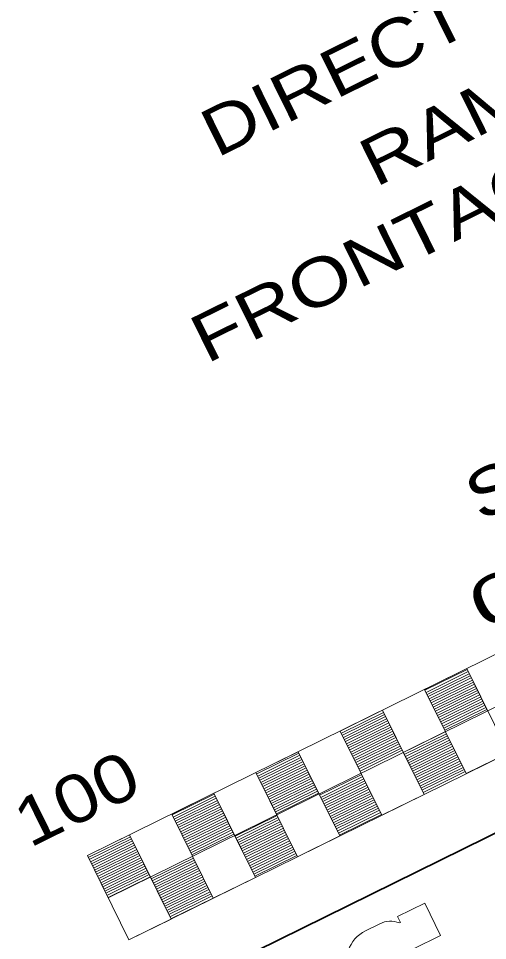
# Model space of a CAD drawing. Extents: x 2356606 to 2371222, y 6973096 to 6982644.
# Drawn here: x 2358140.4 to 2358240.2, y 6973453.7 to 6973650.2 of the extents above; entities that cross this region are included whole.
import ezdxf
from ezdxf.enums import TextEntityAlignment as Align

# ---------------------------------------------------------------- set-up
doc = ezdxf.new("R2010")
doc.units = 0
doc.header["$LTSCALE"] = 2
doc.layers.add('62', color=7, linetype='Continuous', lineweight=13)
doc.layers.add('63', color=7, linetype='Continuous', lineweight=13)

msp = doc.modelspace()

# ---------------------------------------------------------------- linework, layer by layer
at = {"layer": '62', "lineweight": 35}
msp.add_line((2358728.863, 6973716.998), (2358145.069, 6973428.875), dxfattribs=at)
at = {"layer": '62'}
for p, q in [((2358155.076, 6973471.825), (2358513.803, 6973648.869)), ((2358159.503, 6973462.857), (2358518.229, 6973639.901)), ((2358226.91, 6973507.057), (2358235.878, 6973511.484)), ((2358227.13, 6973506.608), (2358236.098, 6973511.034)), ((2358227.352, 6973506.158), (2358236.321, 6973510.585)), ((2358227.573, 6973505.71), (2358236.541, 6973510.137)), ((2358235.79, 6973511.66), (2358240.215, 6973502.692)), ((2358227.795, 6973505.262), (2358236.764, 6973509.688)), ((2358228.017, 6973504.813), (2358236.985, 6973509.24)), ((2358228.237, 6973504.365), (2358237.205, 6973508.791)), ((2358228.458, 6973503.917), (2358237.427, 6973508.343)), ((2358228.679, 6973503.469), (2358237.647, 6973507.895)), ((2358226.822, 6973507.233), (2358231.247, 6973498.265)), ((2358228.901, 6973503.021), (2358237.869, 6973507.446)), ((2358229.123, 6973502.572), (2358238.09, 6973506.998)), ((2358229.343, 6973502.124), (2358238.313, 6973506.549)), ((2358229.566, 6973501.675), (2358238.534, 6973506.101)), ((2358229.787, 6973501.227), (2358238.755, 6973505.652)), ((2358230.008, 6973500.779), (2358238.976, 6973505.204)), ((2358230.229, 6973500.33), (2358239.197, 6973504.756)), ((2358230.449, 6973499.882), (2358239.419, 6973504.307)), ((2358208.89, 6973498.371), (2358217.859, 6973502.798)), ((2358209.111, 6973497.922), (2358218.08, 6973502.349)), ((2358217.854, 6973502.808), (2358222.28, 6973493.84)), ((2358230.671, 6973499.433), (2358239.639, 6973503.859)), ((2358230.892, 6973498.985), (2358239.862, 6973503.411)), ((2358231.115, 6973498.537), (2358240.082, 6973502.962)), ((2358209.334, 6973497.472), (2358218.301, 6973501.899)), ((2358209.556, 6973497.024), (2358218.522, 6973501.452)), ((2358209.776, 6973496.576), (2358218.744, 6973501.002)), ((2358209.997, 6973496.128), (2358218.966, 6973500.554)), ((2358210.219, 6973495.681), (2358219.186, 6973500.106)), ((2358208.885, 6973498.381), (2358213.31, 6973489.414)), ((2358210.439, 6973495.231), (2358219.408, 6973499.657)), ((2358210.662, 6973494.783), (2358219.63, 6973499.209)), ((2358210.883, 6973494.335), (2358219.85, 6973498.761)), ((2358211.103, 6973493.886), (2358220.072, 6973498.313)), ((2358222.284, 6973493.829), (2358231.253, 6973498.256)), ((2358211.324, 6973493.439), (2358220.294, 6973497.863)), ((2358211.546, 6973492.989), (2358220.514, 6973497.415)), ((2358211.768, 6973492.541), (2358220.735, 6973496.967)), ((2358211.988, 6973492.093), (2358220.957, 6973496.519)), ((2358212.21, 6973491.644), (2358221.179, 6973496.071)), ((2358222.506, 6973493.381), (2358231.474, 6973497.808)), ((2358222.727, 6973492.933), (2358231.697, 6973497.36)), ((2358222.949, 6973492.485), (2358231.918, 6973496.911)), ((2358223.169, 6973492.036), (2358232.138, 6973496.463)), ((2358212.432, 6973491.196), (2358221.399, 6973495.622)), ((2358212.652, 6973490.747), (2358221.621, 6973495.174)), ((2358212.875, 6973490.3), (2358221.843, 6973494.726)), ((2358213.096, 6973489.851), (2358222.063, 6973494.277)), ((2358223.391, 6973491.588), (2358232.36, 6973496.015)), ((2358223.613, 6973491.14), (2358232.582, 6973495.566)), ((2358223.833, 6973490.691), (2358232.803, 6973495.118)), ((2358224.054, 6973490.242), (2358233.023, 6973494.669)), ((2358224.276, 6973489.794), (2358233.245, 6973494.221)), ((2358191.1, 6973489.222), (2358200.069, 6973493.647)), ((2358191.321, 6973488.773), (2358200.29, 6973493.199)), ((2358191.543, 6973488.324), (2358200.511, 6973492.75)), ((2358191.765, 6973487.876), (2358200.733, 6973492.301)), ((2358199.917, 6973493.957), (2358204.343, 6973484.987)), ((2358222.279, 6973493.84), (2358226.706, 6973484.871)), ((2358222.28, 6973493.841), (2358226.706, 6973484.872)), ((2358224.498, 6973489.346), (2358233.467, 6973493.773)), ((2358224.719, 6973488.898), (2358233.687, 6973493.324)), ((2358224.939, 6973488.449), (2358233.909, 6973492.876)), ((2358225.162, 6973488.001), (2358234.131, 6973492.428)), ((2358191.986, 6973487.427), (2358200.953, 6973491.854)), ((2358192.208, 6973486.979), (2358201.176, 6973491.406)), ((2358192.428, 6973486.53), (2358201.397, 6973490.957)), ((2358192.649, 6973486.082), (2358201.619, 6973490.509)), ((2358225.383, 6973487.552), (2358234.352, 6973491.978)), ((2358225.605, 6973487.103), (2358234.574, 6973491.53)), ((2358225.825, 6973486.656), (2358234.794, 6973491.081)), ((2358226.046, 6973486.207), (2358235.016, 6973490.633)), ((2358226.268, 6973485.759), (2358235.237, 6973490.184)), ((2358190.948, 6973489.529), (2358195.374, 6973480.561)), ((2358192.872, 6973485.634), (2358201.84, 6973490.06)), ((2358193.093, 6973485.186), (2358202.06, 6973489.612)), ((2358193.313, 6973484.737), (2358202.282, 6973489.164)), ((2358193.535, 6973484.289), (2358202.503, 6973488.715)), ((2358193.756, 6973483.84), (2358202.725, 6973488.267)), ((2358204.495, 6973484.681), (2358213.464, 6973489.106)), ((2358204.716, 6973484.231), (2358213.685, 6973488.658)), ((2358204.937, 6973483.784), (2358213.907, 6973488.21)), ((2358226.489, 6973485.31), (2358235.458, 6973489.736)), ((2358193.978, 6973483.392), (2358202.945, 6973487.818)), ((2358194.198, 6973482.944), (2358203.167, 6973487.37)), ((2358194.421, 6973482.496), (2358203.389, 6973486.922)), ((2358194.642, 6973482.047), (2358203.61, 6973486.473)), ((2358205.159, 6973483.336), (2358214.127, 6973487.761)), ((2358205.38, 6973482.886), (2358214.35, 6973487.313)), ((2358205.6, 6973482.438), (2358214.57, 6973486.863)), ((2358205.822, 6973481.989), (2358214.79, 6973486.415)), ((2358173.097, 6973480.509), (2358182.065, 6973484.935)), ((2358173.318, 6973480.061), (2358182.285, 6973484.486)), ((2358181.98, 6973485.104), (2358186.407, 6973476.137)), ((2358194.862, 6973481.599), (2358203.83, 6973486.025)), ((2358195.084, 6973481.151), (2358204.052, 6973485.576)), ((2358195.304, 6973480.703), (2358204.273, 6973485.129)), ((2358204.343, 6973484.988), (2358208.768, 6973476.02)), ((2358204.343, 6973484.987), (2358208.77, 6973476.019)), ((2358206.043, 6973481.541), (2358215.013, 6973485.967)), ((2358206.264, 6973481.093), (2358215.234, 6973485.519)), ((2358206.486, 6973480.644), (2358215.455, 6973485.071)), ((2358206.708, 6973480.196), (2358215.677, 6973484.621)), ((2358173.54, 6973479.611), (2358182.508, 6973484.039)), ((2358173.761, 6973479.163), (2358182.728, 6973483.589)), ((2358173.982, 6973478.713), (2358182.949, 6973483.141)), ((2358174.203, 6973478.266), (2358183.171, 6973482.693)), ((2358206.929, 6973479.747), (2358215.897, 6973484.175)), ((2358207.151, 6973479.299), (2358216.119, 6973483.727)), ((2358207.37, 6973478.85), (2358216.34, 6973483.278)), ((2358207.592, 6973478.401), (2358216.562, 6973482.829)), ((2358207.814, 6973477.953), (2358216.783, 6973482.38)), ((2358173.013, 6973480.677), (2358177.438, 6973471.71)), ((2358174.424, 6973477.818), (2358183.393, 6973482.244)), ((2358174.646, 6973477.37), (2358183.614, 6973481.797)), ((2358174.867, 6973476.922), (2358183.835, 6973481.347)), ((2358175.088, 6973476.474), (2358184.057, 6973480.899)), ((2358175.31, 6973476.025), (2358184.278, 6973480.452)), ((2358186.49, 6973475.968), (2358195.458, 6973480.392)), ((2358208.035, 6973477.505), (2358217.004, 6973481.932)), ((2358208.257, 6973477.056), (2358217.226, 6973481.484)), ((2358208.478, 6973476.607), (2358217.447, 6973481.034)), ((2358208.699, 6973476.16), (2358217.669, 6973480.587)), ((2358175.531, 6973475.577), (2358184.5, 6973480.002)), ((2358175.752, 6973475.127), (2358184.721, 6973479.554)), ((2358175.973, 6973474.68), (2358184.941, 6973479.105)), ((2358176.195, 6973474.232), (2358185.163, 6973478.657)), ((2358186.711, 6973475.519), (2358195.679, 6973479.944)), ((2358186.933, 6973475.07), (2358195.9, 6973479.496)), ((2358187.154, 6973474.622), (2358196.121, 6973479.047)), ((2358187.375, 6973474.173), (2358196.343, 6973478.599)), ((2358176.416, 6973473.782), (2358185.384, 6973478.208)), ((2358176.636, 6973473.335), (2358185.606, 6973477.761)), ((2358176.859, 6973472.886), (2358185.826, 6973477.312)), ((2358177.08, 6973472.438), (2358186.048, 6973476.863)), ((2358177.302, 6973471.989), (2358186.27, 6973476.415)), ((2358187.597, 6973473.725), (2358196.564, 6973478.15)), ((2358187.817, 6973473.277), (2358196.785, 6973477.702)), ((2358188.039, 6973472.828), (2358197.007, 6973477.254)), ((2358188.26, 6973472.381), (2358197.229, 6973476.805)), ((2358155.267, 6973471.439), (2358164.237, 6973475.863)), ((2358155.49, 6973470.989), (2358164.458, 6973475.415)), ((2358155.71, 6973470.54), (2358164.68, 6973474.967)), ((2358155.933, 6973470.092), (2358164.9, 6973474.518)), ((2358164.045, 6973476.25), (2358168.471, 6973467.283)), ((2358186.405, 6973476.134), (2358190.831, 6973467.166)), ((2358186.407, 6973476.136), (2358190.833, 6973467.167)), ((2358188.482, 6973471.931), (2358197.449, 6973476.358)), ((2358188.703, 6973471.483), (2358197.67, 6973475.91)), ((2358188.925, 6973471.035), (2358197.891, 6973475.461)), ((2358189.146, 6973470.586), (2358198.113, 6973475.013)), ((2358189.367, 6973470.138), (2358198.335, 6973474.564)), ((2358156.153, 6973469.643), (2358165.121, 6973474.069)), ((2358156.375, 6973469.195), (2358165.342, 6973473.621)), ((2358156.596, 6973468.747), (2358165.564, 6973473.173)), ((2358156.817, 6973468.298), (2358165.786, 6973472.725)), ((2358189.59, 6973469.689), (2358198.556, 6973474.116)), ((2358189.809, 6973469.241), (2358198.777, 6973473.666)), ((2358190.032, 6973468.793), (2358198.998, 6973473.218)), ((2358190.252, 6973468.344), (2358199.219, 6973472.77)), ((2358155.076, 6973471.825), (2358159.503, 6973462.857)), ((2358157.039, 6973467.85), (2358166.006, 6973472.276)), ((2358157.259, 6973467.401), (2358166.228, 6973471.828)), ((2358157.481, 6973466.953), (2358166.449, 6973471.379)), ((2358157.702, 6973466.505), (2358166.67, 6973470.932)), ((2358168.662, 6973466.896), (2358177.629, 6973471.321)), ((2358168.883, 6973466.447), (2358177.849, 6973470.872)), ((2358190.473, 6973467.896), (2358199.441, 6973472.321)), ((2358190.695, 6973467.447), (2358199.662, 6973471.873)), ((2358157.923, 6973466.056), (2358166.892, 6973470.484)), ((2358158.145, 6973465.608), (2358167.112, 6973470.035)), ((2358158.366, 6973465.16), (2358167.334, 6973469.587)), ((2358158.588, 6973464.712), (2358167.556, 6973469.138)), ((2358158.809, 6973464.263), (2358167.777, 6973468.69)), ((2358169.104, 6973465.999), (2358178.072, 6973470.424)), ((2358169.326, 6973465.55), (2358178.293, 6973469.976)), ((2358169.547, 6973465.102), (2358178.515, 6973469.528)), ((2358169.769, 6973464.654), (2358178.736, 6973469.079)), ((2358169.989, 6973464.205), (2358178.957, 6973468.631)), ((2358159.029, 6973463.815), (2358167.999, 6973468.241)), ((2358159.25, 6973463.367), (2358168.219, 6973467.793)), ((2358159.472, 6973462.919), (2358168.441, 6973467.345)), ((2358168.471, 6973467.283), (2358172.897, 6973458.315)), ((2358170.211, 6973463.757), (2358179.178, 6973468.181)), ((2358170.432, 6973463.309), (2358179.398, 6973467.734)), ((2358170.652, 6973462.86), (2358179.621, 6973467.286)), ((2358170.875, 6973462.412), (2358179.842, 6973466.837)), ((2358171.096, 6973461.963), (2358180.062, 6973466.389)), ((2358171.318, 6973461.514), (2358180.285, 6973465.94)), ((2358171.539, 6973461.065), (2358180.507, 6973465.491)), ((2358171.759, 6973460.617), (2358180.729, 6973465.043)), ((2358171.981, 6973460.169), (2358180.948, 6973464.593)), ((2358172.202, 6973459.719), (2358181.171, 6973464.146)), ((2358172.424, 6973459.272), (2358181.391, 6973463.698)), ((2358172.645, 6973458.823), (2358181.613, 6973463.25)), ((2358172.866, 6973458.374), (2358181.835, 6973462.802)), ((2358214.276, 6973455.844), (2358217.266, 6973457.32))]:
    msp.add_line(p, q, dxfattribs=at)
for points in [[(2358235.673, 6973489.297), (2358244.642, 6973493.723), (2358235.79, 6973511.66), (2358226.822, 6973507.233)], [(2358217.738, 6973480.444), (2358226.706, 6973484.871), (2358217.854, 6973502.808), (2358208.885, 6973498.381)], [(2358199.801, 6973471.593), (2358208.77, 6973476.019), (2358199.917, 6973493.957), (2358190.948, 6973489.529)], [(2358181.865, 6973462.741), (2358190.833, 6973467.167), (2358181.98, 6973485.104), (2358173.013, 6973480.677)], [(2358163.928, 6973453.889), (2358172.897, 6973458.315), (2358164.045, 6973476.25), (2358155.076, 6973471.825)]]:
    msp.add_lwpolyline(points, close=True, dxfattribs=at)
msp.add_lwpolyline([(2358221.461, 6973457.508), (2358221.678, 6973457.615), (2358221.074, 6973458.839), (2358226.861, 6973461.695), (2358230.242, 6973454.844), (2358224.455, 6973451.988)], dxfattribs=at)
for centre, radius, start, end in [((2358219.577, 6973452.665), 5.197, 68.74309, 116.40675), ((2358217.575, 6973449.254), 7.37, 116.59512, 205.42078)]:
    msp.add_arc(centre, radius, start, end, dxfattribs=at)
at = {"layer": '63'}
for p, q in [((2358155.076, 6973471.825), (2358513.803, 6973648.869)), ((2358159.503, 6973462.857), (2358518.229, 6973639.901)), ((2358163.928, 6973453.889), (2358522.655, 6973630.932)), ((2358226.91, 6973507.057), (2358235.878, 6973511.484)), ((2358227.13, 6973506.608), (2358236.098, 6973511.034)), ((2358227.352, 6973506.158), (2358236.321, 6973510.585)), ((2358227.573, 6973505.71), (2358236.541, 6973510.137)), ((2358235.79, 6973511.66), (2358240.215, 6973502.692)), ((2358227.795, 6973505.262), (2358236.764, 6973509.688)), ((2358228.017, 6973504.813), (2358236.985, 6973509.24)), ((2358228.237, 6973504.365), (2358237.205, 6973508.791)), ((2358228.458, 6973503.917), (2358237.427, 6973508.343)), ((2358228.679, 6973503.469), (2358237.647, 6973507.895)), ((2358226.822, 6973507.233), (2358231.247, 6973498.265)), ((2358228.901, 6973503.021), (2358237.869, 6973507.446)), ((2358229.123, 6973502.572), (2358238.09, 6973506.998)), ((2358229.343, 6973502.124), (2358238.313, 6973506.549)), ((2358229.566, 6973501.675), (2358238.534, 6973506.101)), ((2358229.787, 6973501.227), (2358238.755, 6973505.652)), ((2358230.008, 6973500.779), (2358238.976, 6973505.204)), ((2358230.229, 6973500.33), (2358239.197, 6973504.756)), ((2358230.449, 6973499.882), (2358239.419, 6973504.307)), ((2358208.89, 6973498.371), (2358217.859, 6973502.798)), ((2358209.111, 6973497.922), (2358218.08, 6973502.349)), ((2358217.854, 6973502.808), (2358222.28, 6973493.84)), ((2358230.671, 6973499.433), (2358239.639, 6973503.859)), ((2358230.892, 6973498.985), (2358239.862, 6973503.411)), ((2358231.115, 6973498.537), (2358240.082, 6973502.962)), ((2358209.334, 6973497.472), (2358218.301, 6973501.899)), ((2358209.556, 6973497.024), (2358218.522, 6973501.452)), ((2358209.776, 6973496.576), (2358218.744, 6973501.002)), ((2358209.997, 6973496.128), (2358218.966, 6973500.554)), ((2358210.219, 6973495.681), (2358219.186, 6973500.106)), ((2358208.885, 6973498.381), (2358213.31, 6973489.414)), ((2358210.439, 6973495.231), (2358219.408, 6973499.657)), ((2358210.662, 6973494.783), (2358219.63, 6973499.209)), ((2358210.883, 6973494.335), (2358219.85, 6973498.761)), ((2358211.103, 6973493.886), (2358220.072, 6973498.313)), ((2358222.284, 6973493.829), (2358231.253, 6973498.256)), ((2358211.324, 6973493.439), (2358220.294, 6973497.863)), ((2358211.546, 6973492.989), (2358220.514, 6973497.415)), ((2358211.768, 6973492.541), (2358220.735, 6973496.967)), ((2358211.988, 6973492.093), (2358220.957, 6973496.519)), ((2358212.21, 6973491.644), (2358221.179, 6973496.071)), ((2358222.506, 6973493.381), (2358231.474, 6973497.808)), ((2358222.727, 6973492.933), (2358231.697, 6973497.36)), ((2358222.949, 6973492.485), (2358231.918, 6973496.911)), ((2358223.169, 6973492.036), (2358232.138, 6973496.463)), ((2358212.432, 6973491.196), (2358221.399, 6973495.622)), ((2358212.652, 6973490.747), (2358221.621, 6973495.174)), ((2358212.875, 6973490.3), (2358221.843, 6973494.726)), ((2358213.096, 6973489.851), (2358222.063, 6973494.277)), ((2358223.391, 6973491.588), (2358232.36, 6973496.015)), ((2358223.613, 6973491.14), (2358232.582, 6973495.566)), ((2358223.833, 6973490.691), (2358232.803, 6973495.118)), ((2358224.054, 6973490.242), (2358233.023, 6973494.669)), ((2358224.276, 6973489.794), (2358233.245, 6973494.221)), ((2358191.1, 6973489.222), (2358200.069, 6973493.647)), ((2358191.321, 6973488.773), (2358200.29, 6973493.199)), ((2358191.543, 6973488.324), (2358200.511, 6973492.75)), ((2358191.765, 6973487.876), (2358200.733, 6973492.301)), ((2358199.917, 6973493.957), (2358204.343, 6973484.987)), ((2358222.279, 6973493.84), (2358226.706, 6973484.871)), ((2358222.28, 6973493.841), (2358226.706, 6973484.872)), ((2358224.498, 6973489.346), (2358233.467, 6973493.773)), ((2358224.719, 6973488.898), (2358233.687, 6973493.324)), ((2358224.939, 6973488.449), (2358233.909, 6973492.876)), ((2358225.162, 6973488.001), (2358234.131, 6973492.428)), ((2358191.986, 6973487.427), (2358200.953, 6973491.854)), ((2358192.208, 6973486.979), (2358201.176, 6973491.406)), ((2358192.428, 6973486.53), (2358201.397, 6973490.957)), ((2358192.649, 6973486.082), (2358201.619, 6973490.509)), ((2358225.383, 6973487.552), (2358234.352, 6973491.978)), ((2358225.605, 6973487.103), (2358234.574, 6973491.53)), ((2358225.825, 6973486.656), (2358234.794, 6973491.081)), ((2358226.046, 6973486.207), (2358235.016, 6973490.633)), ((2358226.268, 6973485.759), (2358235.237, 6973490.184)), ((2358190.948, 6973489.529), (2358195.374, 6973480.561)), ((2358192.872, 6973485.634), (2358201.84, 6973490.06)), ((2358193.093, 6973485.186), (2358202.06, 6973489.612)), ((2358193.313, 6973484.737), (2358202.282, 6973489.164)), ((2358193.535, 6973484.289), (2358202.503, 6973488.715)), ((2358193.756, 6973483.84), (2358202.725, 6973488.267)), ((2358204.495, 6973484.681), (2358213.464, 6973489.106)), ((2358204.716, 6973484.231), (2358213.685, 6973488.658)), ((2358204.937, 6973483.784), (2358213.907, 6973488.21)), ((2358226.489, 6973485.31), (2358235.458, 6973489.736)), ((2358193.978, 6973483.392), (2358202.945, 6973487.818)), ((2358194.198, 6973482.944), (2358203.167, 6973487.37)), ((2358194.421, 6973482.496), (2358203.389, 6973486.922)), ((2358194.642, 6973482.047), (2358203.61, 6973486.473)), ((2358205.159, 6973483.336), (2358214.127, 6973487.761)), ((2358205.38, 6973482.886), (2358214.35, 6973487.313)), ((2358205.6, 6973482.438), (2358214.57, 6973486.863)), ((2358205.822, 6973481.989), (2358214.79, 6973486.415)), ((2358173.097, 6973480.509), (2358182.065, 6973484.935)), ((2358173.318, 6973480.061), (2358182.285, 6973484.486)), ((2358181.98, 6973485.104), (2358186.407, 6973476.137)), ((2358194.862, 6973481.599), (2358203.83, 6973486.025)), ((2358195.084, 6973481.151), (2358204.052, 6973485.576)), ((2358195.304, 6973480.703), (2358204.273, 6973485.129)), ((2358204.343, 6973484.988), (2358208.768, 6973476.02)), ((2358204.343, 6973484.987), (2358208.77, 6973476.019)), ((2358206.043, 6973481.541), (2358215.013, 6973485.967)), ((2358206.264, 6973481.093), (2358215.234, 6973485.519)), ((2358206.486, 6973480.644), (2358215.455, 6973485.071)), ((2358206.708, 6973480.196), (2358215.677, 6973484.621)), ((2358173.54, 6973479.611), (2358182.508, 6973484.039)), ((2358173.761, 6973479.163), (2358182.728, 6973483.589)), ((2358173.982, 6973478.713), (2358182.949, 6973483.141)), ((2358174.203, 6973478.266), (2358183.171, 6973482.693)), ((2358206.929, 6973479.747), (2358215.897, 6973484.175)), ((2358207.151, 6973479.299), (2358216.119, 6973483.727)), ((2358207.37, 6973478.85), (2358216.34, 6973483.278)), ((2358207.592, 6973478.401), (2358216.562, 6973482.829)), ((2358207.814, 6973477.953), (2358216.783, 6973482.38)), ((2358173.013, 6973480.677), (2358177.438, 6973471.71)), ((2358174.424, 6973477.818), (2358183.393, 6973482.244)), ((2358174.646, 6973477.37), (2358183.614, 6973481.797)), ((2358174.867, 6973476.922), (2358183.835, 6973481.347)), ((2358175.088, 6973476.474), (2358184.057, 6973480.899)), ((2358175.31, 6973476.025), (2358184.278, 6973480.452)), ((2358186.49, 6973475.968), (2358195.458, 6973480.392)), ((2358208.035, 6973477.505), (2358217.004, 6973481.932)), ((2358208.257, 6973477.056), (2358217.226, 6973481.484)), ((2358208.478, 6973476.607), (2358217.447, 6973481.034)), ((2358208.699, 6973476.16), (2358217.669, 6973480.587)), ((2358175.531, 6973475.577), (2358184.5, 6973480.002)), ((2358175.752, 6973475.127), (2358184.721, 6973479.554)), ((2358175.973, 6973474.68), (2358184.941, 6973479.105)), ((2358176.195, 6973474.232), (2358185.163, 6973478.657)), ((2358186.711, 6973475.519), (2358195.679, 6973479.944)), ((2358186.933, 6973475.07), (2358195.9, 6973479.496)), ((2358187.154, 6973474.622), (2358196.121, 6973479.047)), ((2358187.375, 6973474.173), (2358196.343, 6973478.599)), ((2358176.416, 6973473.782), (2358185.384, 6973478.208)), ((2358176.636, 6973473.335), (2358185.606, 6973477.761)), ((2358176.859, 6973472.886), (2358185.826, 6973477.312)), ((2358177.08, 6973472.438), (2358186.048, 6973476.863)), ((2358177.302, 6973471.989), (2358186.27, 6973476.415)), ((2358187.597, 6973473.725), (2358196.564, 6973478.15)), ((2358187.817, 6973473.277), (2358196.785, 6973477.702)), ((2358188.039, 6973472.828), (2358197.007, 6973477.254)), ((2358188.26, 6973472.381), (2358197.229, 6973476.805)), ((2358155.267, 6973471.439), (2358164.237, 6973475.863)), ((2358155.49, 6973470.989), (2358164.458, 6973475.415)), ((2358155.71, 6973470.54), (2358164.68, 6973474.967)), ((2358155.933, 6973470.092), (2358164.9, 6973474.518)), ((2358164.045, 6973476.25), (2358168.471, 6973467.283)), ((2358186.405, 6973476.134), (2358190.831, 6973467.166)), ((2358186.407, 6973476.136), (2358190.833, 6973467.167)), ((2358188.482, 6973471.931), (2358197.449, 6973476.358)), ((2358188.703, 6973471.483), (2358197.67, 6973475.91)), ((2358188.925, 6973471.035), (2358197.891, 6973475.461)), ((2358189.146, 6973470.586), (2358198.113, 6973475.013)), ((2358189.367, 6973470.138), (2358198.335, 6973474.564)), ((2358156.153, 6973469.643), (2358165.121, 6973474.069)), ((2358156.375, 6973469.195), (2358165.342, 6973473.621)), ((2358156.596, 6973468.747), (2358165.564, 6973473.173)), ((2358156.817, 6973468.298), (2358165.786, 6973472.725)), ((2358189.59, 6973469.689), (2358198.556, 6973474.116)), ((2358189.809, 6973469.241), (2358198.777, 6973473.666)), ((2358190.032, 6973468.793), (2358198.998, 6973473.218)), ((2358190.252, 6973468.344), (2358199.219, 6973472.77)), ((2358155.076, 6973471.825), (2358159.503, 6973462.857)), ((2358157.039, 6973467.85), (2358166.006, 6973472.276)), ((2358157.259, 6973467.401), (2358166.228, 6973471.828)), ((2358157.481, 6973466.953), (2358166.449, 6973471.379)), ((2358157.702, 6973466.505), (2358166.67, 6973470.932)), ((2358168.662, 6973466.896), (2358177.629, 6973471.321)), ((2358168.883, 6973466.447), (2358177.849, 6973470.872)), ((2358190.473, 6973467.896), (2358199.441, 6973472.321)), ((2358190.695, 6973467.447), (2358199.662, 6973471.873)), ((2358157.923, 6973466.056), (2358166.892, 6973470.484)), ((2358158.145, 6973465.608), (2358167.112, 6973470.035)), ((2358158.366, 6973465.16), (2358167.334, 6973469.587)), ((2358158.588, 6973464.712), (2358167.556, 6973469.138)), ((2358158.809, 6973464.263), (2358167.777, 6973468.69)), ((2358169.104, 6973465.999), (2358178.072, 6973470.424)), ((2358169.326, 6973465.55), (2358178.293, 6973469.976)), ((2358169.547, 6973465.102), (2358178.515, 6973469.528)), ((2358169.769, 6973464.654), (2358178.736, 6973469.079)), ((2358169.989, 6973464.205), (2358178.957, 6973468.631)), ((2358159.029, 6973463.815), (2358167.999, 6973468.241)), ((2358159.25, 6973463.367), (2358168.219, 6973467.793)), ((2358159.472, 6973462.919), (2358168.441, 6973467.345)), ((2358168.471, 6973467.283), (2358172.897, 6973458.315)), ((2358170.211, 6973463.757), (2358179.178, 6973468.181)), ((2358170.432, 6973463.309), (2358179.398, 6973467.734)), ((2358170.652, 6973462.86), (2358179.621, 6973467.286)), ((2358170.875, 6973462.412), (2358179.842, 6973466.837)), ((2358171.096, 6973461.963), (2358180.062, 6973466.389)), ((2358171.318, 6973461.514), (2358180.285, 6973465.94)), ((2358171.539, 6973461.065), (2358180.507, 6973465.491)), ((2358171.759, 6973460.617), (2358180.729, 6973465.043)), ((2358171.981, 6973460.169), (2358180.948, 6973464.593)), ((2358172.202, 6973459.719), (2358181.171, 6973464.146)), ((2358172.424, 6973459.272), (2358181.391, 6973463.698)), ((2358172.645, 6973458.823), (2358181.613, 6973463.25)), ((2358172.866, 6973458.374), (2358181.835, 6973462.802))]:
    msp.add_line(p, q, dxfattribs=at)
for points in [[(2358235.673, 6973489.297), (2358244.642, 6973493.723), (2358235.79, 6973511.66), (2358226.822, 6973507.233)], [(2358217.738, 6973480.444), (2358226.706, 6973484.871), (2358217.854, 6973502.808), (2358208.885, 6973498.381)], [(2358199.801, 6973471.593), (2358208.77, 6973476.019), (2358199.917, 6973493.957), (2358190.948, 6973489.529)], [(2358181.865, 6973462.741), (2358190.833, 6973467.167), (2358181.98, 6973485.104), (2358173.013, 6973480.677)], [(2358163.928, 6973453.889), (2358172.897, 6973458.315), (2358164.045, 6973476.25), (2358155.076, 6973471.825)]]:
    msp.add_lwpolyline(points, close=True, dxfattribs=at)

# ---------------------------------------------------------------- texts
at = {"layer": '62'}
for s, width, p in [('DIRECT CONNECTOR & RAMP DESIGN SPEED = 50 MPH', 1.2, (2358381.426, 6973718.525)), ('FRONTAGE ROAD DESIGN SPEED VARIABLE 35 TO 40 MPH', 1.25, (2358399.194, 6973684.505)), ('RAMP DESIGN SPEED VARIABLE 40 TO 50 MPH', 1.25, (2358390.532, 6973700.074)), ('SCALE:  1 INCH = 100 FT.', 1.2, (2358326.677, 6973586.227)), ('0', 1.55, (2358244.759, 6973522.259)), ('100', 1.2, (2358155.027, 6973479.448))]:
    msp.add_text(s, height=10.2, rotation=26.268, dxfattribs=dict(at, width=width)).set_placement(p, align=Align.CENTER)
at = {"layer": '62', "width": 1.25}
for s, p in [('3010 LBJ Freeway, Suite 1300', (2358191.148, 6973365.269)), ('Graystone Centre', (2358181.612, 6973384.592))]:
    msp.add_text(s, height=13.22, rotation=26.268, dxfattribs=at).set_placement(p)
at = {"layer": '63'}
for s, width, p in [('DIRECT CONNECTOR & RAMP DESIGN SPEED = 50 MPH', 1.2, (2358381.426, 6973718.525)), ('0', 1.55, (2358244.759, 6973522.259)), ('100', 1.2, (2358155.027, 6973479.448))]:
    msp.add_text(s, height=10.2, rotation=26.268, dxfattribs=dict(at, width=width)).set_placement(p, align=Align.CENTER)

doc.saveas('drawing.dxf')
